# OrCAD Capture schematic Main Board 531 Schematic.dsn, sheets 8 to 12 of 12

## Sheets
8 08 COMET SYSTEM: size A3; title: COMET10 EVAL board - Clock, JTAG, SPI0, Tamper
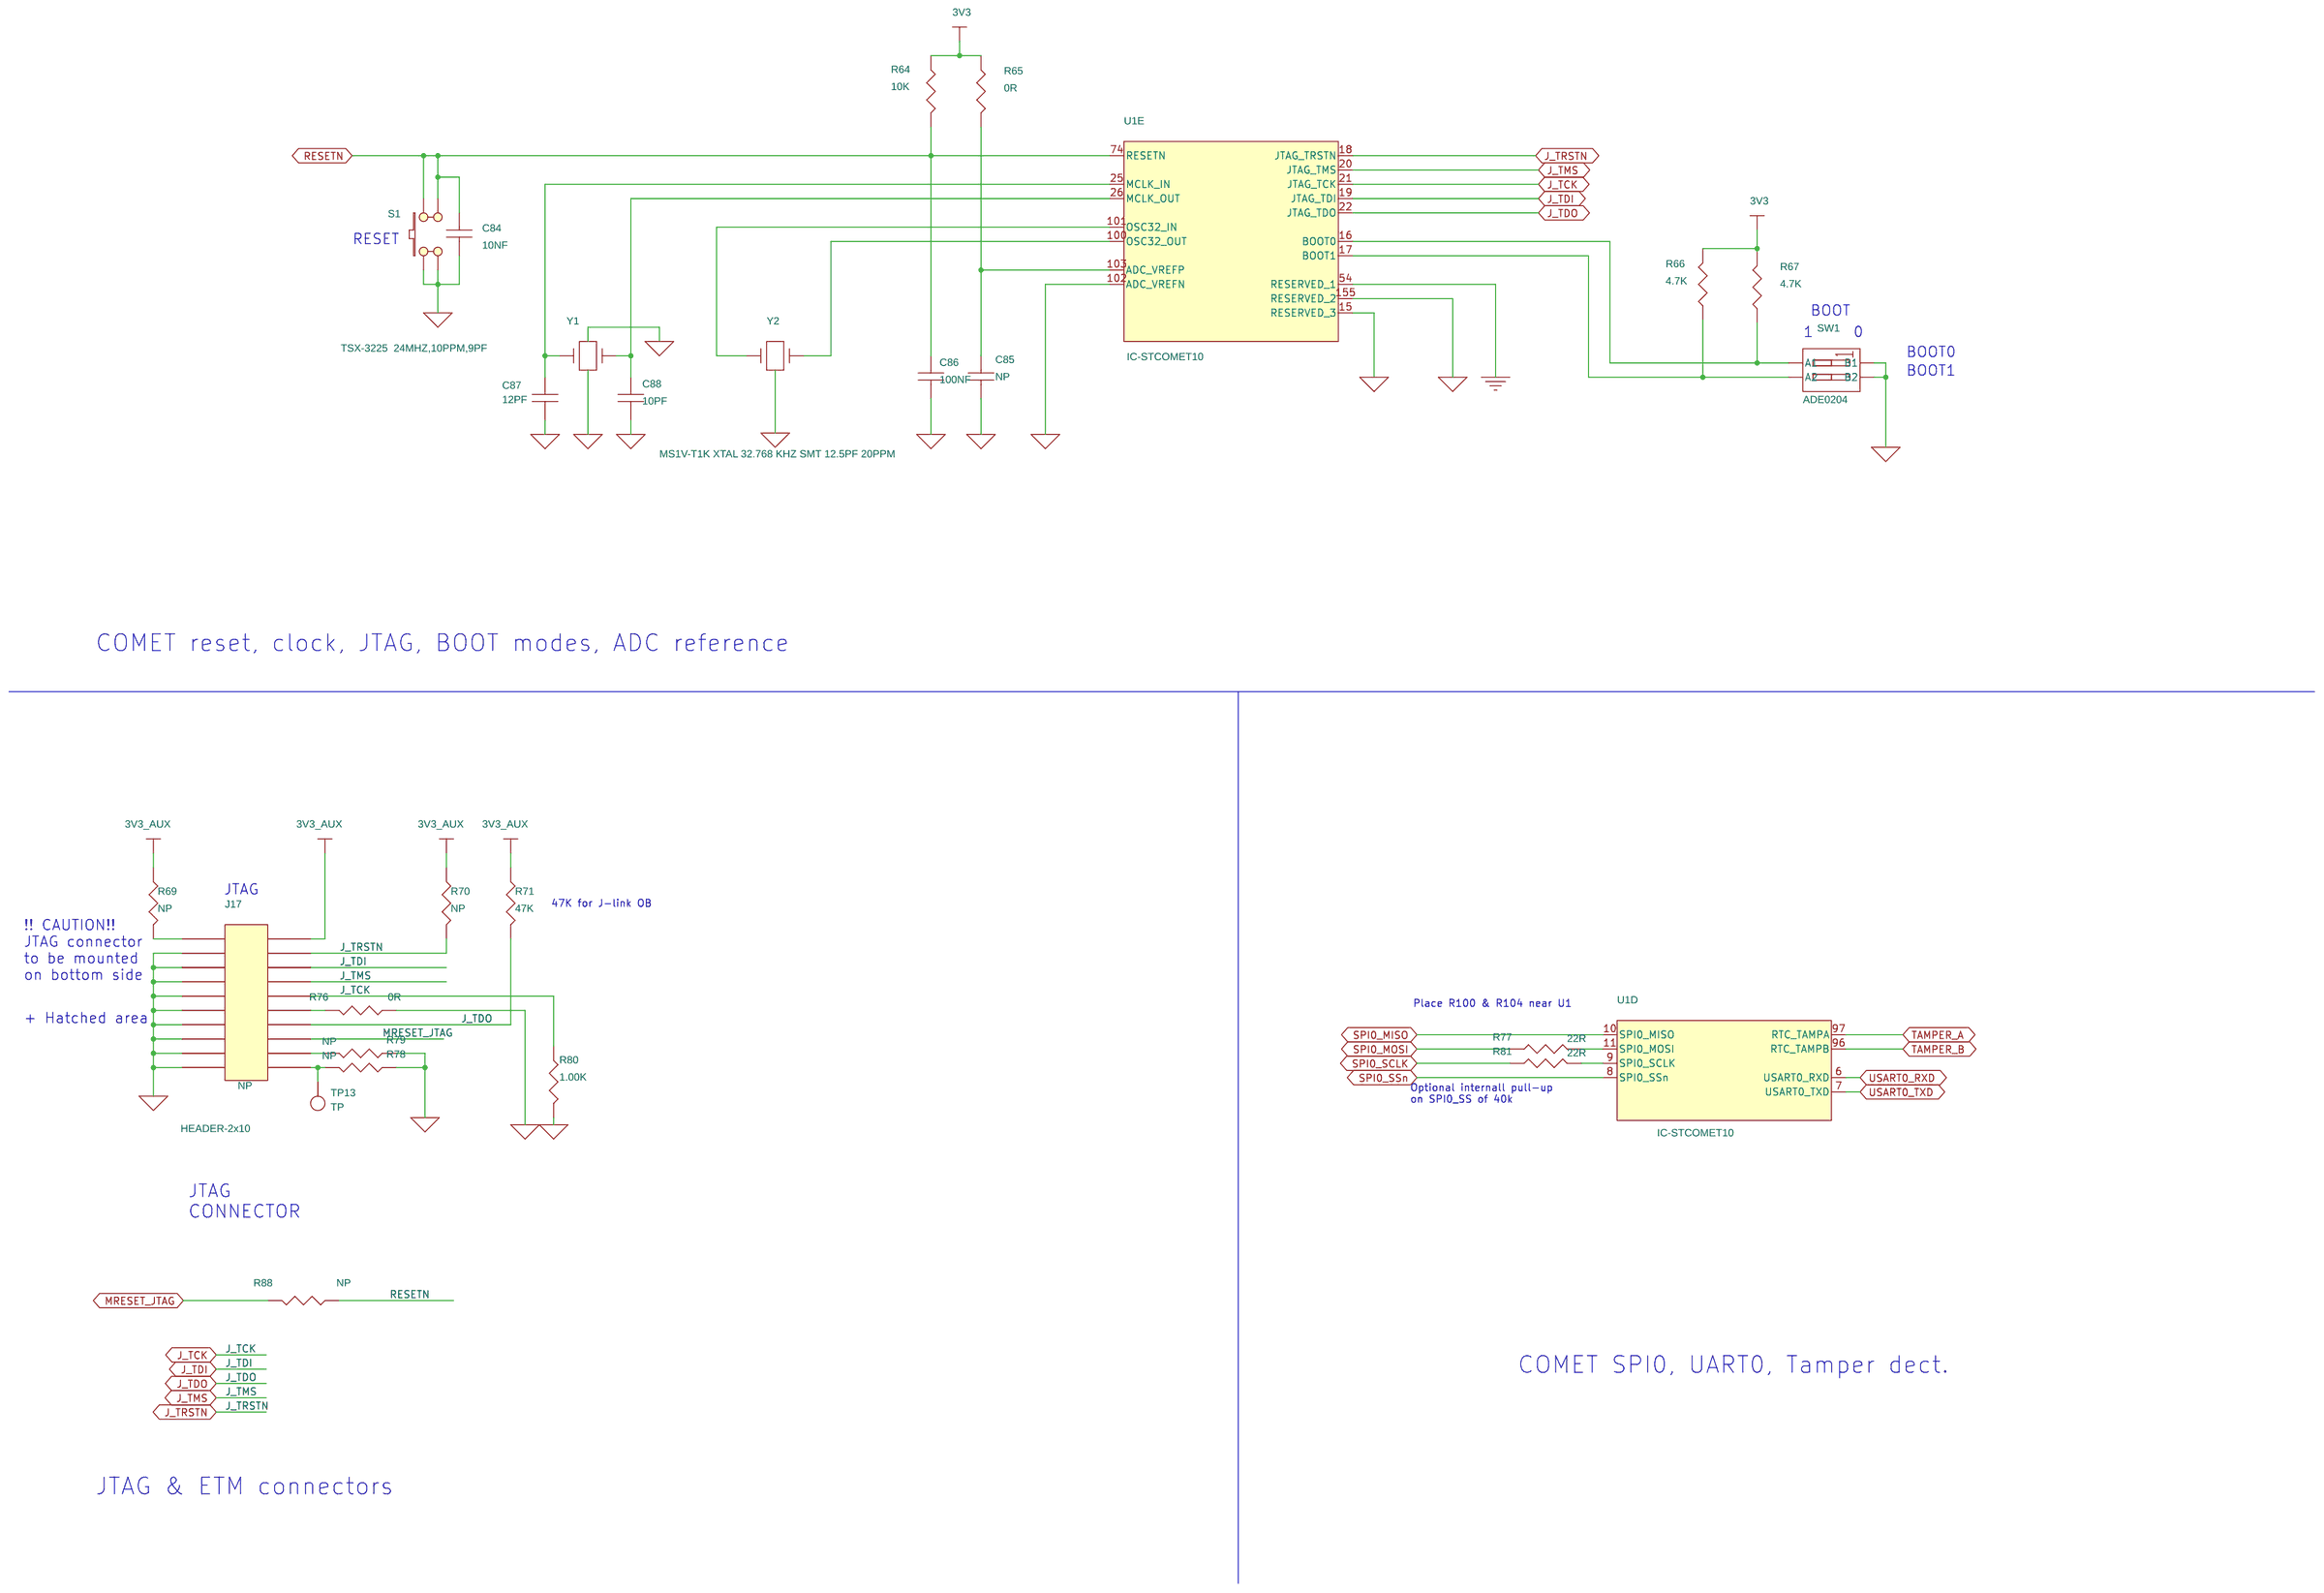
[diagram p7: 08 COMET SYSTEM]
9 09 COMET GPIO: size A3; title: COMET10 EVAL board - COMET GPIOs
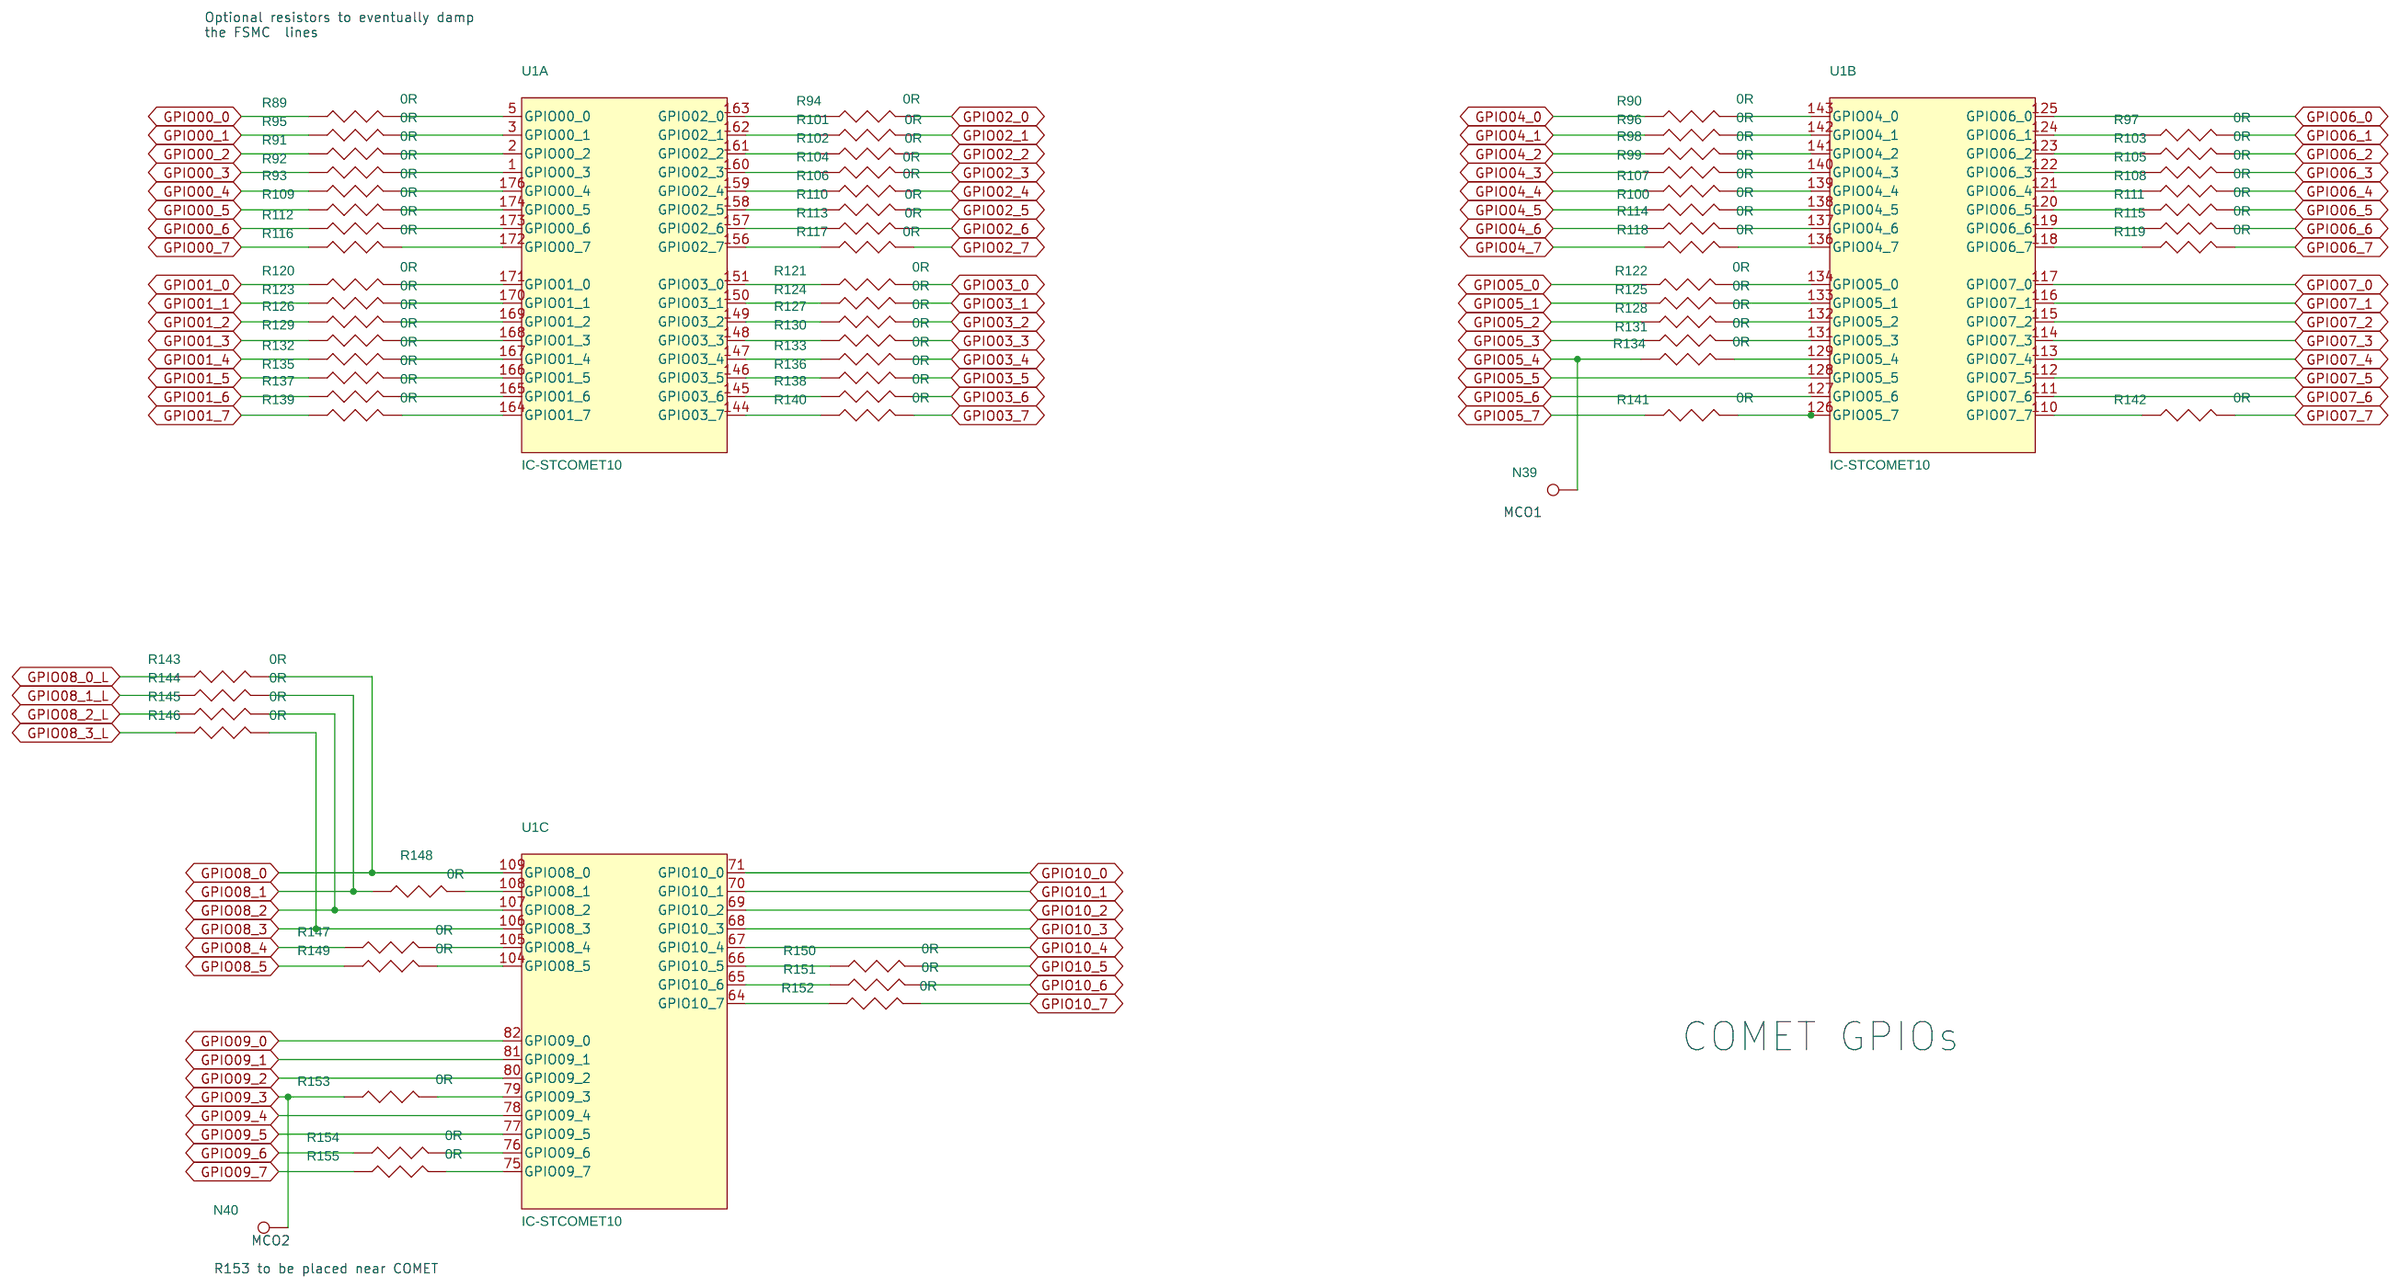
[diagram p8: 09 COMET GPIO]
10 10 MODULE-CONNECTOR: size A3; title: COMET10 EVAL board -  MODULE connector
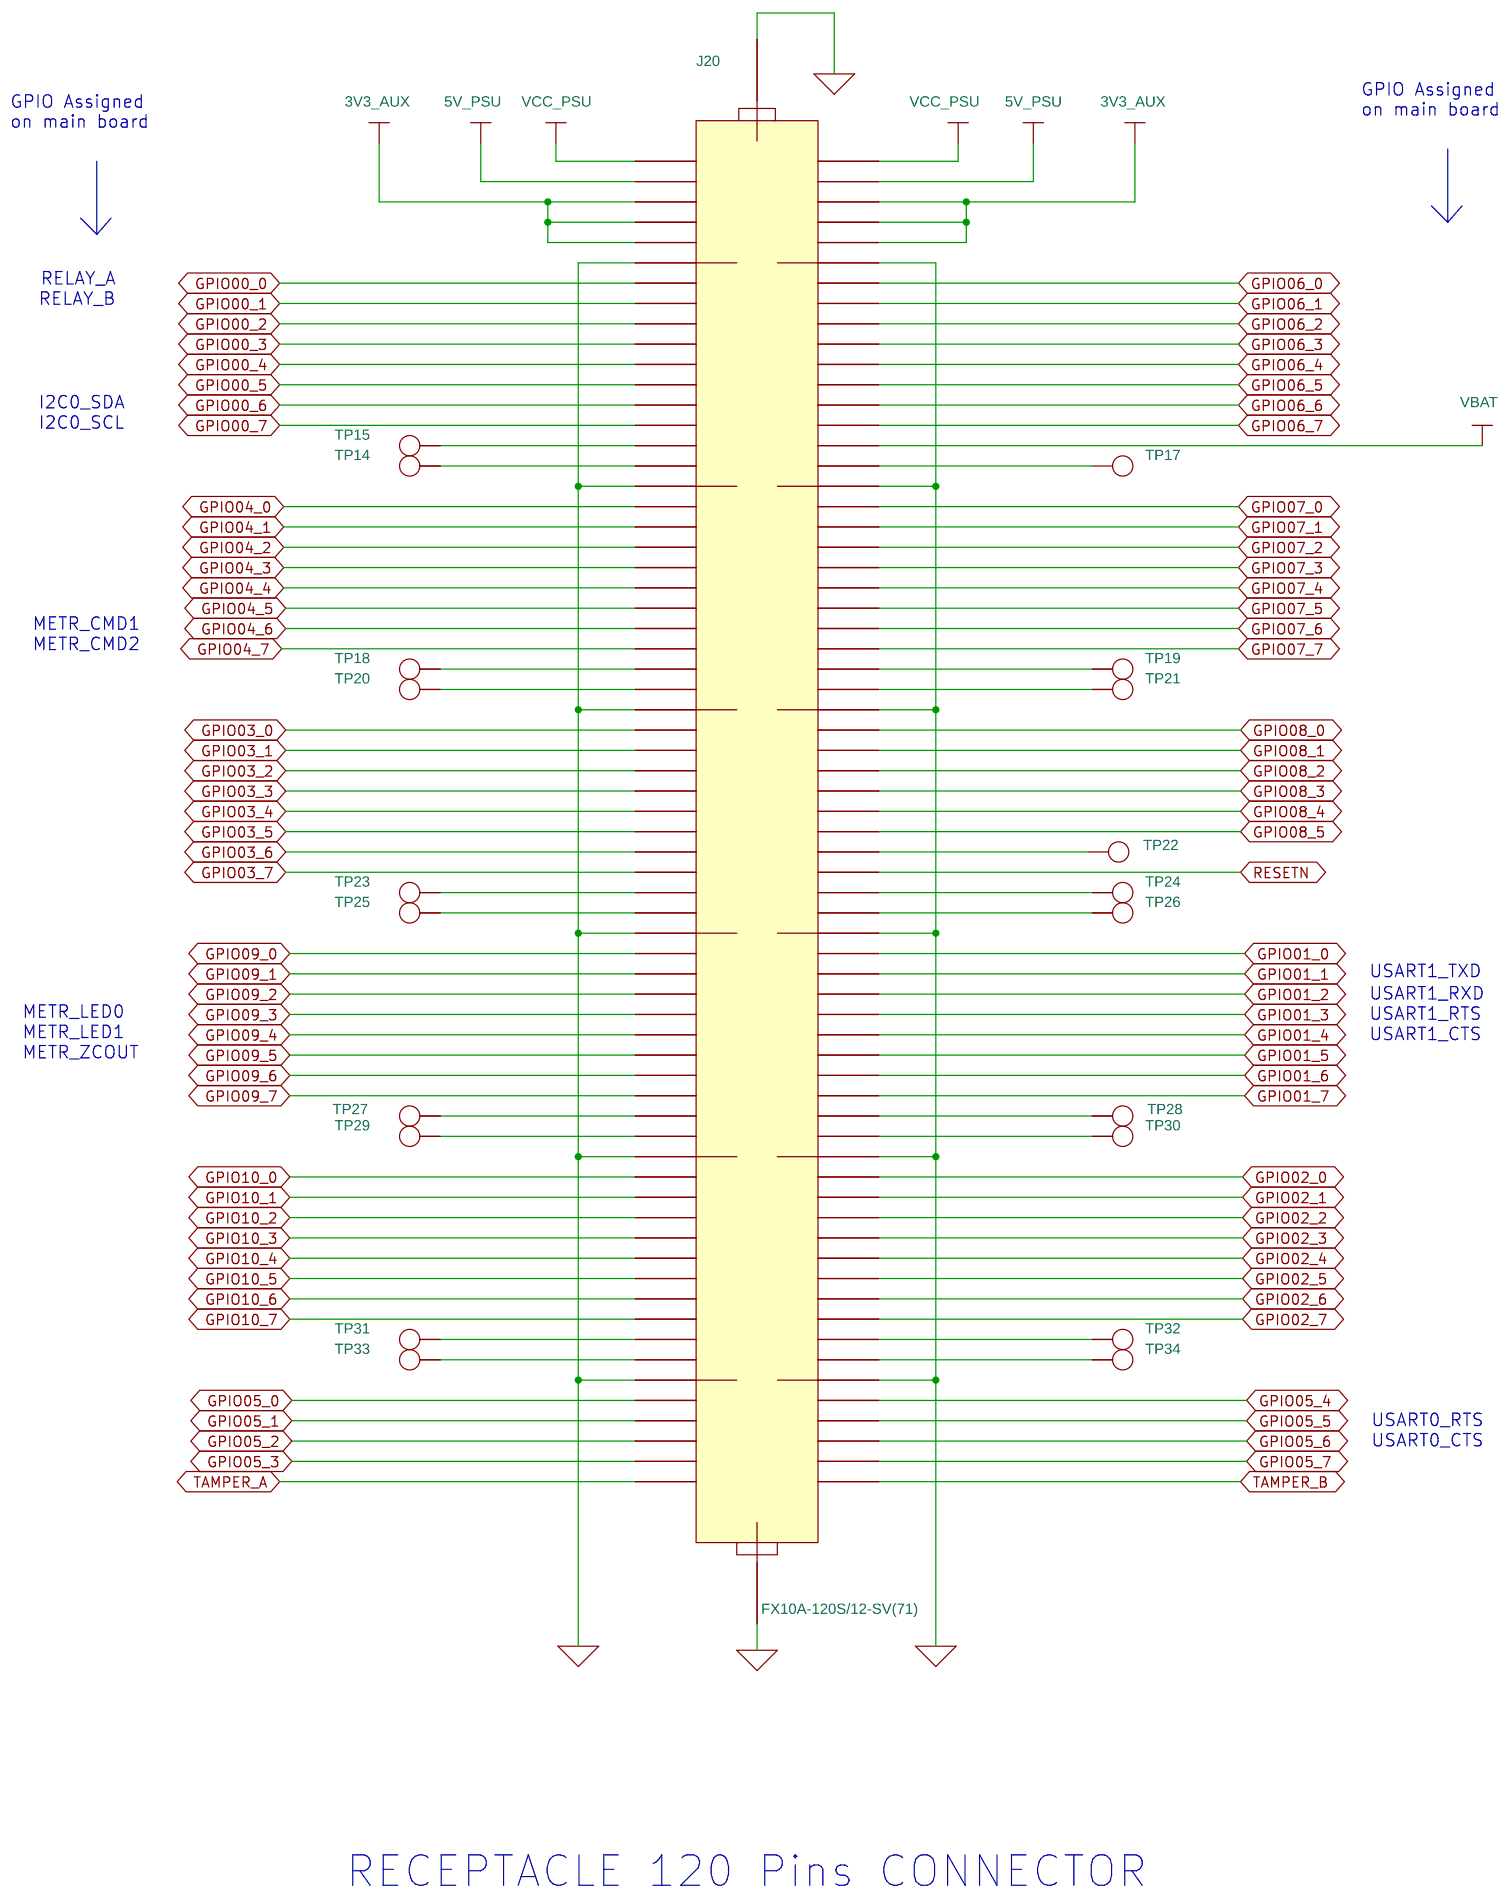
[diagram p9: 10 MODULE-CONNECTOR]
11 11 UART  Switch&Leds: size A3; title: COMET10 EVAL board - USB UART bridge,  DIP Switch&LEDs,EEPROM, SPI FLASH
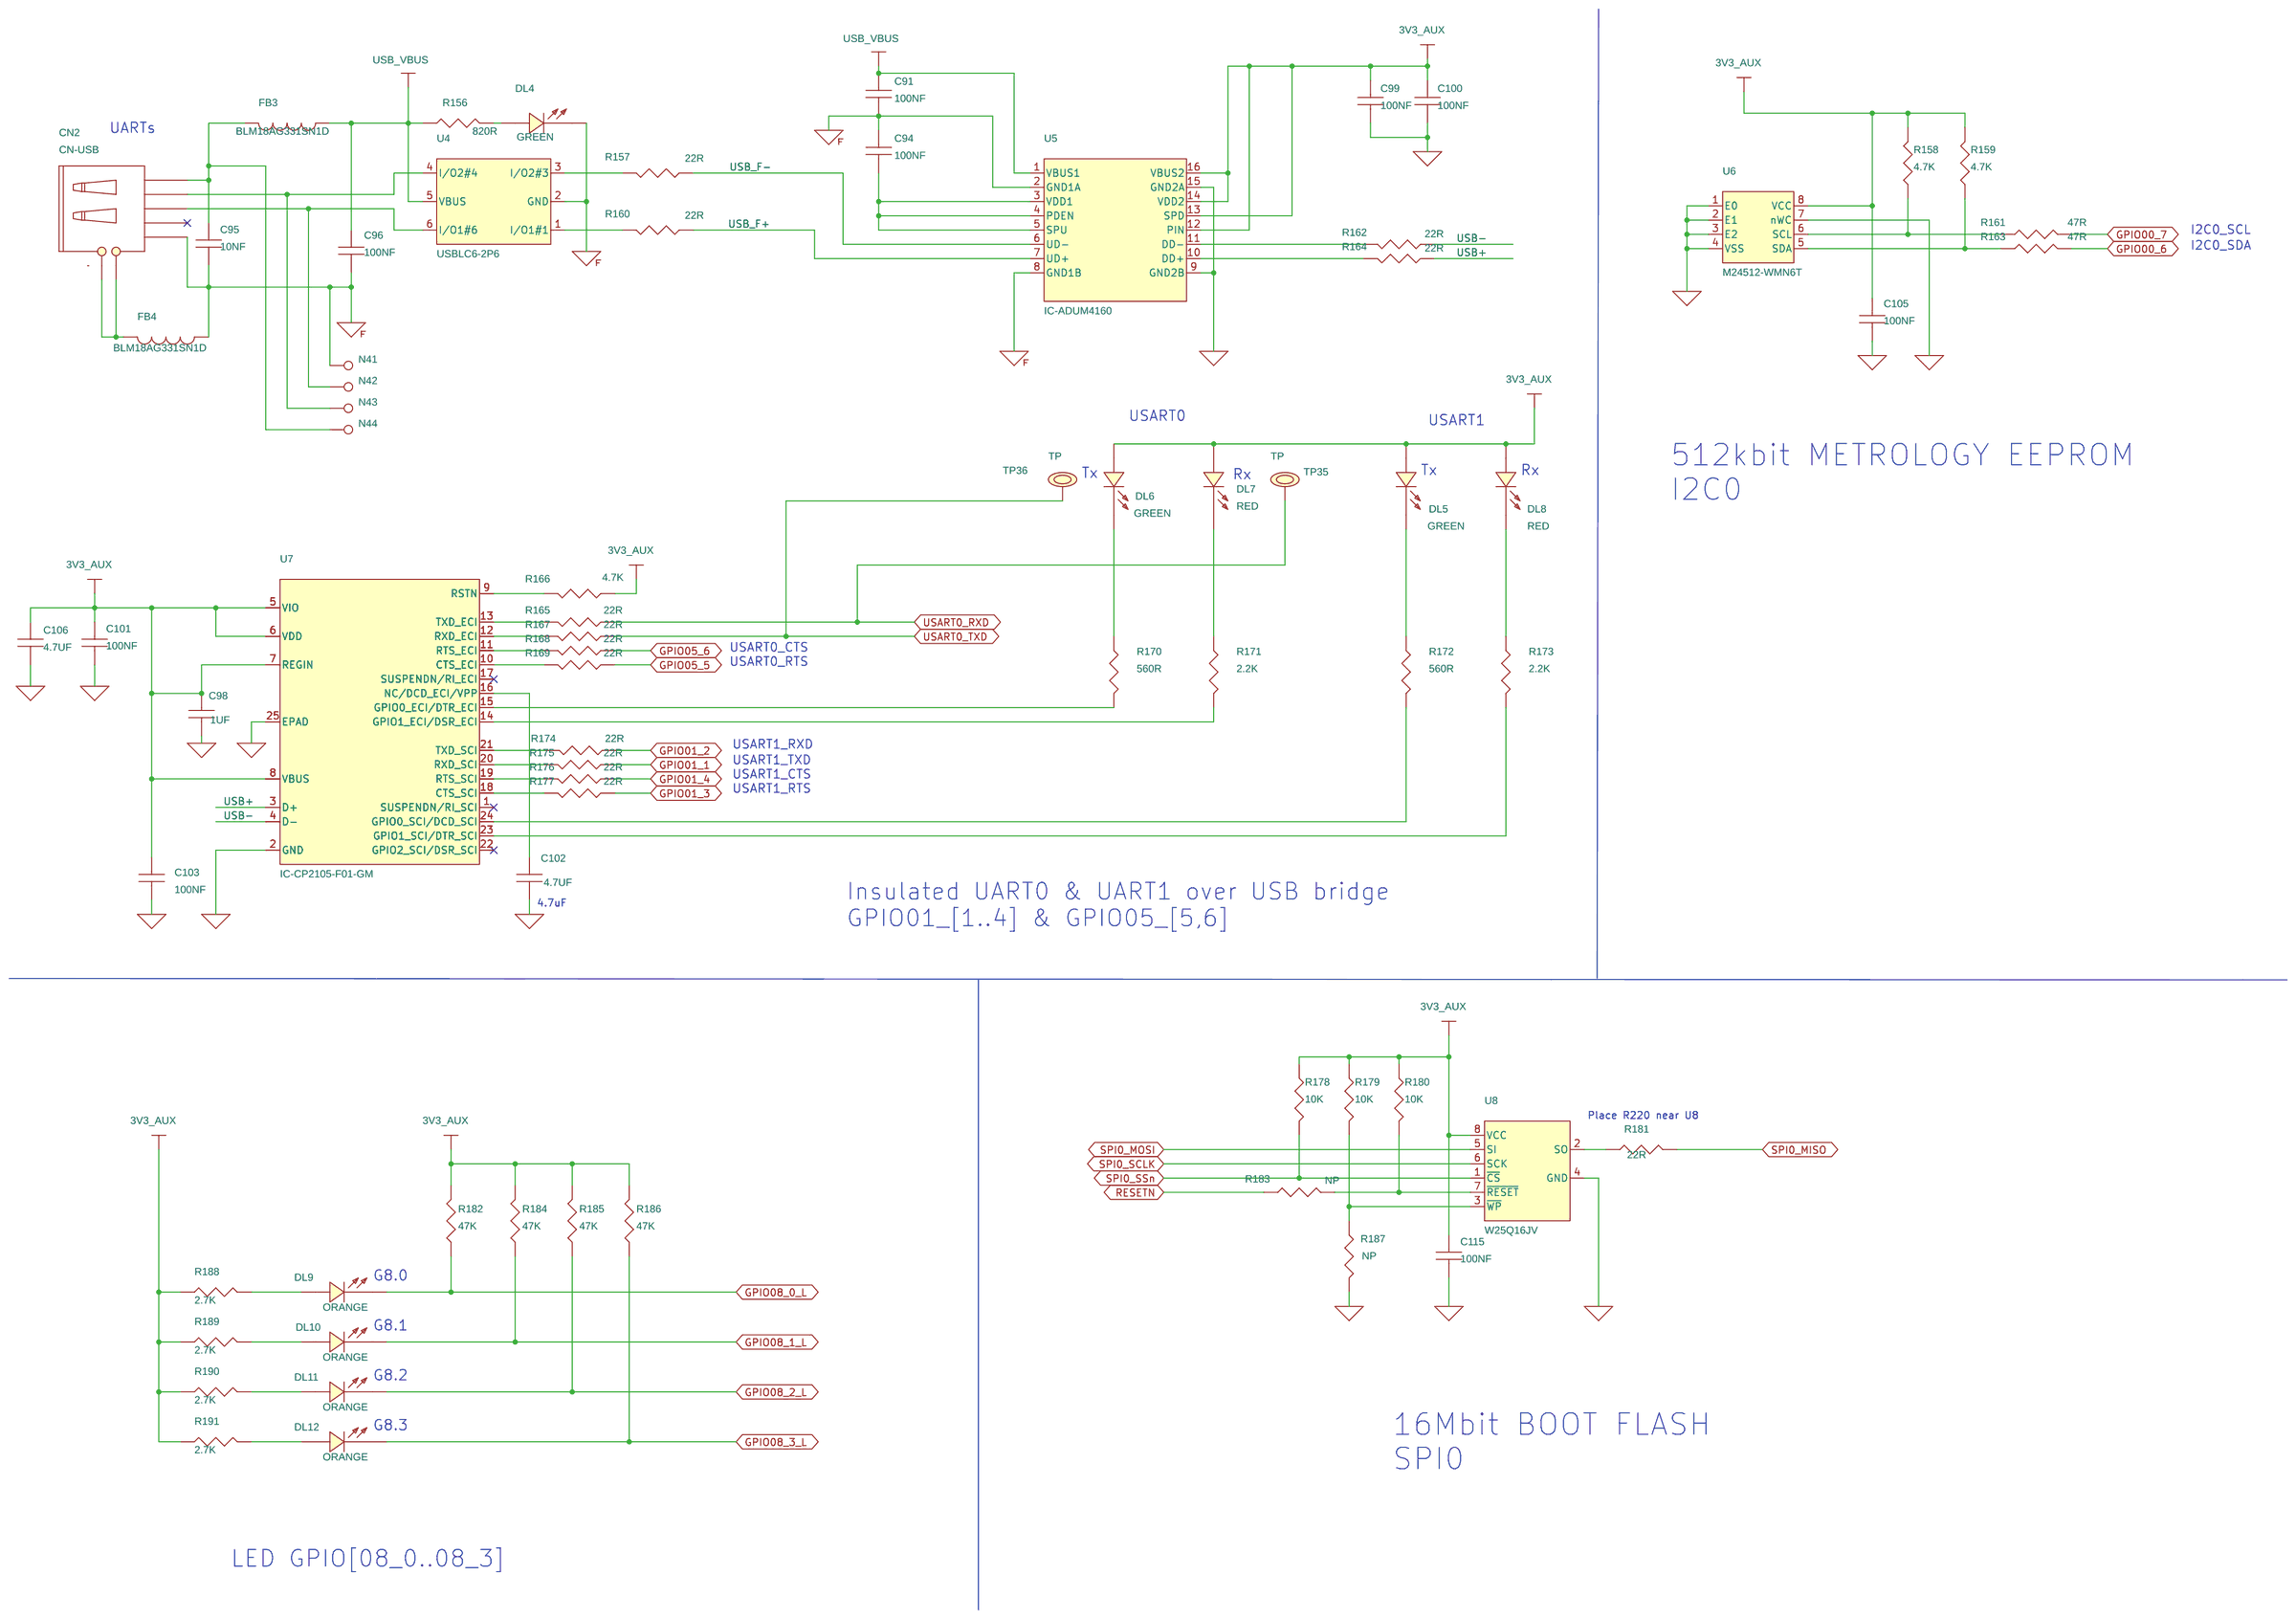
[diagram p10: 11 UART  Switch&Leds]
12 12 J-LINK OB JTAG: size A3; title: COMET10 EVAL Board -  J-LINK OB JTAG
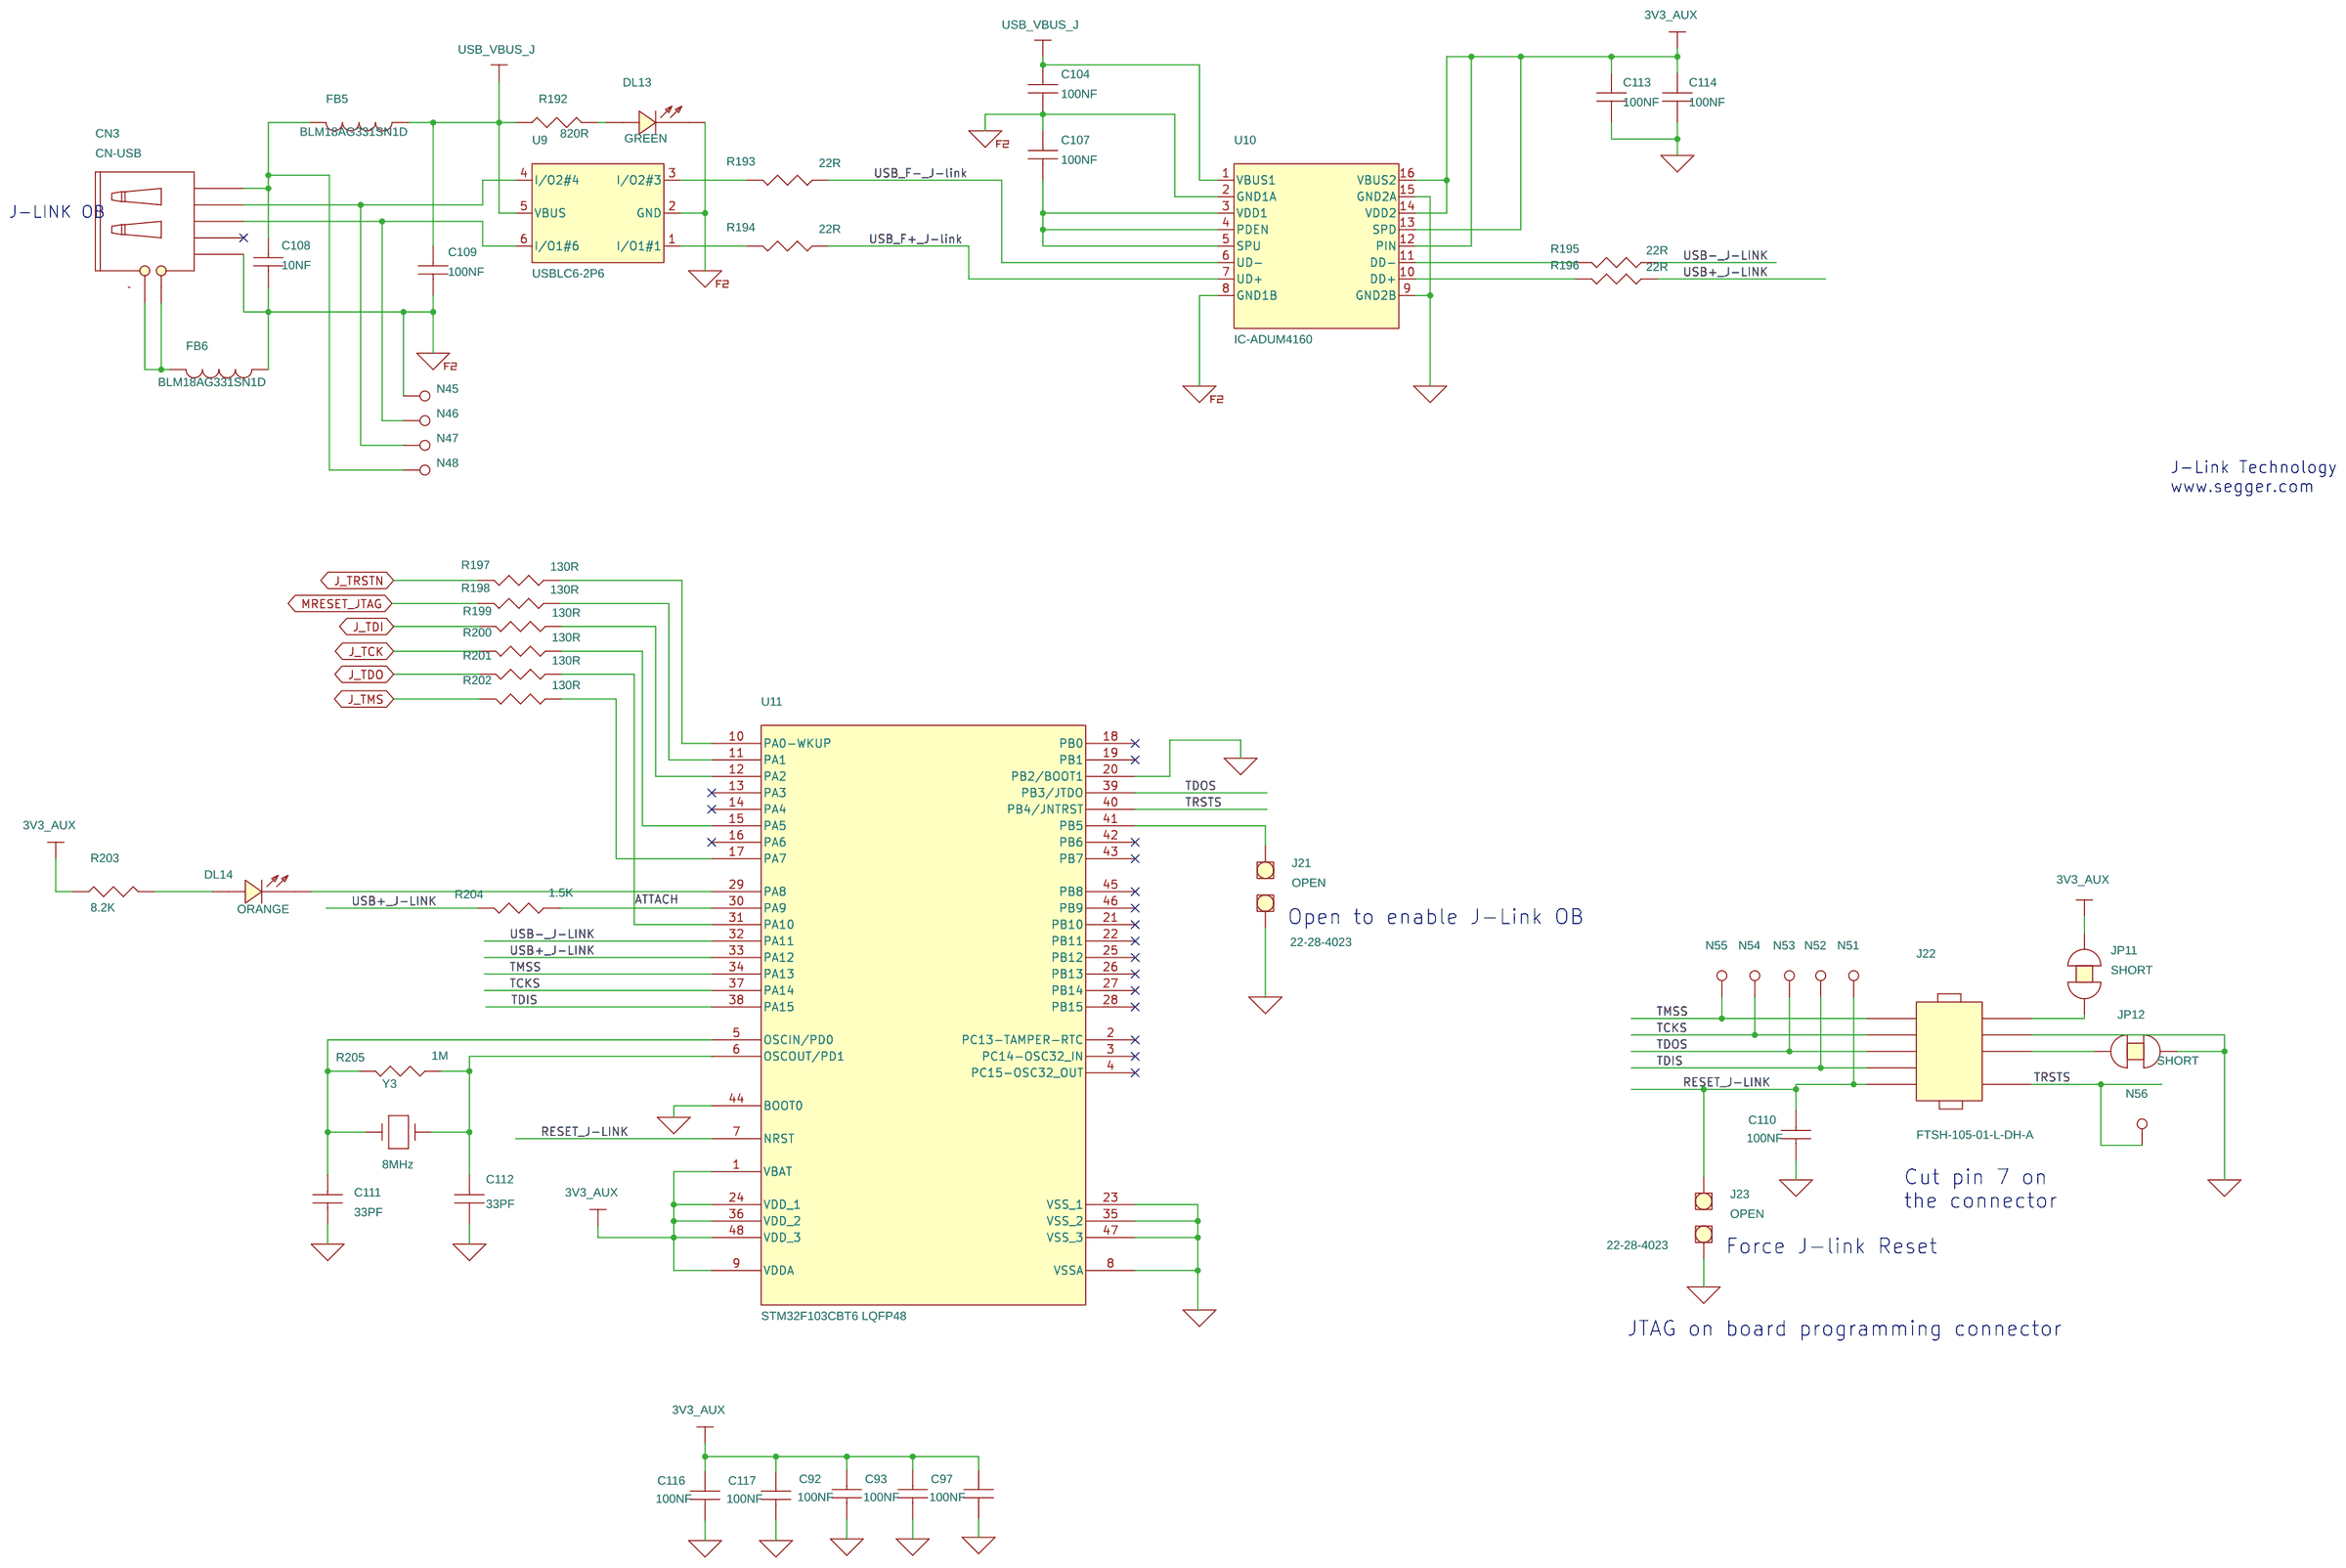
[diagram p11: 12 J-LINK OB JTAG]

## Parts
sheet 04 COMET METROLOGY
U1  IC-STCOMET10  [TQFP176  0.4picth 20*20]  (sections A,B,C,D,E,F,G,H,I,J,K)
sheet 08 COMET SYSTEM
C84  10NF  [0603]
C85  NP  [0402]
C86  100NF  [0402]
C87  12PF  [0603]
C88  10PF  [0603]
J17  NP  [HEADER-2x10]
R64  10K  [0603]
R65  0R  [0603]
R66  4.7K  [0603]
R67  4.7K  [0603]
R69  NP  [0603]
R70  NP  [0603]
R71  47K  [0603]
R76  0R  [0603]
R77  22R  [0603]
R78  NP  [0603]
R79  NP  [0603]
R80  1.00K  [0603]
R81  22R  [0603]
R88  NP  [0603]
S1  EVQQ2H03W  [BUTTON-EVQQ2]
SW1  ADE0204
TP13  TP  [TPSMD-40RD]
Y1  TSX-3225  24MHZ,10PPM,9PF  [OSC-320X250X100-4PIN]
Y2  MS1V-T1K XTAL 32.768 KHZ SMT 12.5PF 20PPM  [XTAL-MS1VT1K]
sheet 09 COMET GPIO
N39  TP  [TPSMD-40RD]
N40  TP  [TPSMD-40RD]
R89  0R  [0603]
R90  0R  [0603]
R91  0R  [0603]
R92  0R  [0603]
R93  0R  [0603]
R94  0R  [0603]
R95  0R  [0603]
R96  0R  [0603]
R97  0R  [0603]
R98  0R  [0603]
R99  0R  [0603]
R100  0R  [0603]
R101  0R  [0603]
R102  0R  [0603]
R103  0R  [0603]
R104  0R  [0603]
R105  0R  [0603]
R106  0R  [0603]
R107  0R  [0603]
R108  0R  [0603]
R109  0R  [0603]
R110  0R  [0603]
R111  0R  [0603]
R112  0R  [0603]
R113  0R  [0603]
R114  0R  [0603]
R115  0R  [0603]
R116  0R  [0603]
R117  0R  [0603]
R118  0R  [0603]
R119  0R  [0603]
R120  0R  [0603]
R121  0R  [0603]
R122  0R  [0603]
R123  0R  [0603]
R124  0R  [0603]
R125  0R  [0603]
R126  0R  [0603]
R127  0R  [0603]
R128  0R  [0603]
R129  0R  [0603]
R130  0R  [0603]
R131  0R  [0603]
R132  0R  [0603]
R133  0R  [0603]
R134  0R  [0603]
R135  0R  [0603]
R136  0R  [0603]
R137  0R  [0603]
R138  0R  [0603]
R139  0R  [0603]
R140  0R  [0603]
R141  0R  [0603]
R142  0R  [0603]
R143  0R  [0603]
R144  0R  [0603]
R145  0R  [0603]
R146  0R  [0603]
R147  0R  [0603]
R148  0R  [0603]
R149  0R  [0603]
R150  0R  [0603]
R151  0R  [0603]
R152  0R  [0603]
R153  0R  [0603]
R154  0R  [0603]
R155  0R  [0603]
sheet 10 MODULE-CONNECTOR
J20  FX10A-120S/12-SV(71)  [FX10A-120S/12-SV(71)-COMET]
TP14  TP  [TPSMD-40RD]
TP15  TP  [TPSMD-40RD]
TP17  TP  [TPSMD-40RD]
TP18  TP  [TPSMD-40RD]
TP19  TP  [TPSMD-40RD]
TP20  TP  [TPSMD-40RD]
TP21  TP  [TPSMD-40RD]
TP22  TP  [TPSMD-40RD]
TP23  TP  [TPSMD-40RD]
TP24  TP  [TPSMD-40RD]
TP25  TP  [TPSMD-40RD]
TP26  TP  [TPSMD-40RD]
TP27  TP  [TPSMD-40RD]
TP28  TP  [TPSMD-40RD]
TP29  TP  [TPSMD-40RD]
TP30  TP  [TPSMD-40RD]
TP31  TP  [TPSMD-40RD]
TP32  TP  [TPSMD-40RD]
TP33  TP  [TPSMD-40RD]
TP34  TP  [TPSMD-40RD]
sheet 11 UART  Switch&Leds
C91  100NF  [0402]
C94  100NF  [0402]
C95  10NF  [0603]
C96  100NF  [0402]
C98  1UF  [0603]
C99  100NF  [0402]
C100  100NF  [0402]
C101  100NF  [0402]
C102  4.7UF  [0603]
C103  100NF  [0402]
C105  100NF  [0402]
C106  4.7UF  [0603]
C115  100NF  [0402]
CN2  CN-USB  [USBMB-HRS-UX60SC]
DL4  GREEN  [LEDC-0603]
DL5  GREEN  [LEDC-0603]
DL6  GREEN  [LEDC-0603]
DL7  RED  [LEDC-0603]
DL8  RED  [LEDC-0603]
DL9  ORANGE  [LEDC-0603]
DL10  ORANGE  [LEDC-0603]
DL11  ORANGE  [LEDC-0603]
DL12  ORANGE  [LEDC-0603]
FB3  BLM18AG331SN1D  [0603]
FB4  BLM18AG331SN1D  [0603]
N41  TP  [TPSMD-40RD]
N42  TP  [TPSMD-40RD]
N43  TP  [TPSMD-40RD]
N44  TP  [TPSMD-40RD]
R156  820R  [0603]
R157  22R  [0603]
R158  4.7K  [0603]
R159  4.7K  [0603]
R160  22R  [0603]
R161  47R  [0603]
R162  22R  [0603]
R163  47R  [0603]
R164  22R  [0603]
R165  22R  [0603]
R166  4.7K  [0603]
R167  22R  [0603]
R168  22R  [0603]
R169  22R  [0603]
R170  560R  [0603]
R171  2.2K  [0603]
R172  560R  [0603]
R173  2.2K  [0603]
R174  22R  [0603]
R175  22R  [0603]
R176  22R  [0603]
R177  22R  [0603]
R178  10K  [0603]
R179  10K  [0603]
R180  10K  [0603]
R181  22R  [0603]
R182  47K  [0603]
R183  NP  [0603]
R184  47K  [0603]
R185  47K  [0603]
R186  47K  [0603]
R187  NP  [0603]
R188  2.7K  [0603]
R189  2.7K  [0603]
R190  2.7K  [0603]
R191  2.7K  [0603]
TP35  TP  [TPTH-ANELLO-1MM]
TP36  TP  [TPTH-ANELLO-1MM]
U4  USBLC6-2P6  [SOT-666]
U5  IC-ADUM4160  [SOC16]
U6  M24512-WMN6T  [SO8]
U7  IC-CP2105-F01-GM  [QFN050P-400X400X080-24-EP]
U8  W25Q16JV  [8NSOIC]
sheet 12 J-LINK OB JTAG
C92  100NF  [0402]
C93  100NF  [0402]
C97  100NF  [0402]
C104  100NF  [0402]
C107  100NF  [0402]
C108  10NF  [0603]
C109  100NF  [0402]
C110  100NF  [0402]
C111  33PF  [0603]
C112  33PF  [0603]
C113  100NF  [0402]
C114  100NF  [0402]
C116  100NF  [0402]
C117  100NF  [0402]
CN3  CN-USB  [USBMB-HRS-UX60SC]
DL13  GREEN  [LEDC-0603]
DL14  ORANGE  [LEDC-0603]
FB5  BLM18AG331SN1D  [0603]
FB6  BLM18AG331SN1D  [0603]
J21  OPEN  [22-28-4023]
J22  FTSH-105-01-L-DH-A  [FTSH-105-01-L-DH-A]
J23  OPEN  [22-28-4023]
JP11  SHORT  [JP2SO]
JP12  SHORT  [JP2SO]
N45  TP  [TPSMD-40RD]
N46  TP  [TPSMD-40RD]
N47  TP  [TPSMD-40RD]
N48  TP  [TPSMD-40RD]
N51  TP  [TPSMD-40RD]
N52  TP  [TPSMD-40RD]
N53  TP  [TPSMD-40RD]
N54  TP  [TPSMD-40RD]
N55  TP  [TPSMD-40RD]
N56  TP  [TPSMD-40RD]
R192  820R  [0603]
R193  22R  [0603]
R194  22R  [0603]
R195  22R  [0603]
R196  22R  [0603]
R197  130R  [0603]
R198  130R  [0603]
R199  130R  [0603]
R200  130R  [0603]
R201  130R  [0603]
R202  130R  [0603]
R203  8.2K  [0603]
R204  1.5K  [0603]
R205  1M  [0603]
U9  USBLC6-2P6  [SOT-666]
U10  IC-ADUM4160  [SOC16]
U11  STM32F103CBT6 LQFP48  [LQFP48]
Y3  8MHz  [ATS08ASM]

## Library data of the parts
U1 = IC-COMET10: Manufacturer: STMICROELECTRONICS; Package_Type: COMET10
C84 C95 C108 = CAP_NP: CAP CER 10nF 25V X7R 0603; Manufacturer: AVX; Manufacturer Part Number: 06033C103KAT2A; PSpice: C; Package_Type: C0603; Part Number: 06033C103KAT2A; Part Type: CERAMIC; Tolerance: 10%; Voltage: 25V
C85 = CAP_NP: CAP NP 0402; PSpice: C; Package_Type: C0402; Part Number: C_NP_0402
C86 C91-C94 C96 C97 C99-C101 C103-C105 C107 C109 C110 C113-C117 = CAP_NP: CAP CER 100nF 16V X7R 0402; Manufacturer: MURATA; Manufacturer Part Number: GRM155R71C104KA88D; PSpice: C; Package_Type: C0402; Part Number: GRM155R71C104KA88D; Part Type: CERAMIC; Tolerance: 10%; Voltage: 16V
C87 = CAP_NP: CAP CER 12pF 50V COG 0603; PSpice: C; Package_Type: C0603; Part Number: 12PF_50V_COG_0603; Part Type: CERAMIC; Tolerance: 10%; Voltage: 50V
C88 = CAP_NP: CAP CER 10PF 50V COG 0603; PSpice: C; Package_Type: C0603; Part Number: 10PF_50V_COG_0603; Part Type: CERAMIC; Tolerance: 10%; Voltage: 50V
J17 = HTST-110-01-T-DV_0: CON-RIGHT ANGLE-10X2-180M; Distributor: FARNELL; Distributor Part Number: 1801424; Manufacturer: SAMTEC; Manufacturer Part Number: TST-110-04-L-D; Package_Type: TST-110-04-L-D; Part Number: TST-110-04-L-D_NP; Datasheet: http://www.samtec.com/ftppub/cpdf/TST-MKT.pdf
R64 R178-R180 = R: RES 10K OHM 5% 1/10W 0603 SMD; Package_Type: R0603; Part Number: 10K_5%_0603; Part type: CMS; Power: 1/10W; Tolerance: 5%
R65 R76 R89-R155 = R: 0.0 OHM 5% 1/10W 0603; Manufacturer: YAGEO; Manufacturer Part Number: RC0603JR-070RL; Package_Type: R0603; Part Number: RC0603JR-070RL; Part type: CMS; Power: 1/10W; Tolerance: 5%
R66 R67 R158 R159 R166 = R: 4.7K OHM 5% 1/10W; Manufacturer: PANASONIC CORP; Manufacturer Part Number: ERJ-3GEYJ472V; Package_Type: R0603; Part Number: ERJ-3GEYJ472V; Part type: CMS; Power: 1/10W; Tolerance: 5%
R69 R70 R78 R79 R88 R183 R187 = R: RES NP 0603; Package_Type: R0603; Part Number: R_NP_0603; Part type: CMS
R71 R182 R184-R186 = R: 47K OHM 1% 1/10W; Manufacturer: PANASONIC CORP; Manufacturer Part Number: ERJ-3EKF4702V; Package_Type: R0603; Part Number: ERJ-3EKF4702V; Part type: CMS; Power: 1/10W; Tolerance: 1%
R77 R81 R157 R160 R162 R164 R165 R167-R169 R174-R177 R181 R193-R196 = R: RES 22.0 OHM 1/10W 5% 0603 SMD; Package_Type: R0603; Part Number: 22R_5%_0603; Part type: CMS; Power: 1/10W; Tolerance: 5%
R80 = R: RESISTOR,  1.00K OHM 1/10W 1% 0603 SMD; ActivepartsID: http://CDS2.ORCAD.COM/default.asp?PID=1783654; ICA_MFR_NAME: PANASONIC CORP; ICA_PARTNUM: $$1783654$$ERJ-3EKF1001V; Manufacturer: PANASONIC CORP; Manufacturer Part Number: ERJ-3EKF1001V; Package_Type: R0603; Part Number: ERJ-3EKF1001V; Part type: CMS; Power: 1/10W; Tolerance: 1%; Datasheet: http://www.panasonic.com/industrial_oem/electronic_components/pdf/erj_precision.pdf
S1 = PULSANTE-EVQQ2_0: SWITCH BUTTON SMD; Distributor: Farnell; Distributor Part Number: 1821248; Manufacturer: PANASONIC CORP; Package_type: BUTTON_EVQQ2; Datasheet: http://fr.farnell.com/panasonic/evqq2h03w/switch-smd-6-5x6x3-1mm-1n/dp/1821248
SW1 = DIPSW-2Channels: DIP Switch 2 channels; Distributor: Farnell; Distributor Part Number: 1123936; Manufacturer: TE CONNECTIVITY; Datasheet: http://www.farnell.com/datasheets/17891.pdf
TP13-TP15 TP17-TP34 = TPSMD-40RD: Point Test PCB TPSMD-40RD
Y1 = XTAL-TSX-3225_0: XTAL,24MHZ,10PPM,9PF; Manufacturer: MICRO CRYSTAL; Manufacturer Part Number: MS1VT1K; Package_type: OSC-EPSON-TSX3225; Part Number: TSX-3225_0; Tolerance: 10PPM; Datasheet: http://fr.farnell.com/micro-crystal/ms1v-t1k-32-768khz-20ppm-12-5pf/crystal-smd-met-32-768khz-12-5/dp/1539359
Y2 = XTAL-MS1VT1K: XTAL 32.768 KHZ SMT 12.5PF 20PPM; Distributor: RS; Distributor Part Number: 672-7590; Manufacturer: Micro Crystal; Manufacturer Part Number: MS1V-T1K 32.768kHz 12.5pF +-20ppm; Part Number: MS1V-T1K 32.768kHz 12.5pF +-20ppm; Tolerance: 20PPM; Datasheet: http://docs-europe.electrocomponents.com/webdocs/0d2c/0900766b80d2cbaf.pdf
N39-N48 N51-N56 = NEEDLE_PAD: Pad 1.7mm for test needle; Package_Type: TPSMD-1.7MM; Part Number: NEEDLE-PAD-1.7mm
J20 = CON-FX10-120P-F-GND: CONN 120P high density EMBASE RECEPTACLE. 0.5MM. GUIDE. 120 VOIES, with reversed pins for COMET; Manufacturer: HIROSE; Package_Type: FX10A-120S/12-SV_COMET; Part Number: FX10A-120S/12-SV(71)-COMET-Mother; Datasheet: \\pouilly.rns.st.com\home\_RDC\External_DataSheet\Connectors\Board_to_Board\Hirose\FXxx\en_FX10_20110101.pdf
C98 = CAP_NP: CAP CER 1UF 10V X7R 0603; PSpice: C; Package_Type: C0603; Part Number: 1UF_10V_X7R_0603; Part Type: CERAMIC; Tolerance: 15%; Voltage: 10V
C102 C106 = CAP_NP: CAP CER 4.7UF 6V3 X5R 0603; PSpice: C; Package_Type: C0603; Part Number: 4.7UF_6V3_X5R_0603; Part Type: CERAMIC; Tolerance: 15%; Voltage: 6.3V
CN2 CN3 = USBMB-HRS-UX60SC: CONN Mini USB2.0 SMT; Distributor: FARNELL; Distributor Part Number: 2300434; Manufacturer: HIROSE; Manufacturer Part Number: UX60SC-MB-5ST; Package_Type: CON-USB-MOLEX-54819-0519; Part Number: UX60SC-MB-5ST; Datasheet: http://uk.farnell.com/hrs-hirose/ux60sc-mb-5st-80/connector-mini-usb-b-receptacle/dp/2300434?Ntt=2300434
DL4-DL6 DL13 = LED: GREEN LEDC-0603; Distributor: RS; Distributor Part Number: 692-1007; Manufacturer: LITE-ON; Manufacturer Part Number: LTST-C191GKT; Package_Type: LEDC-0603_GREEN; Part Number: LED_GREEN_0603_2mA; Datasheet: http://docs-europe.electrocomponents.com/webdocs/0dc0/0900766b80dc02af.pdf
DL7 DL8 = LED: RED LEDC-0603; Distributor: RS; Distributor Part Number: 692-1041; Manufacturer: LITE-ON; Manufacturer Part Number: LTST-C193KRKT-5A; Package_Type: LEDC-0603_RED; Part Number: LED_RED_0603_2mA; Datasheet: http://docs-europe.electrocomponents.com/webdocs/0dc0/0900766b80dc0551.pdf
DL9-DL12 DL14 = LED: ORANGE LEDC-0603; Distributor: RS; Distributor Part Number: 692-1001; Manufacturer: LITE-ON; Manufacturer Part Number: LTST-C191KFKT; Package_Type: LEDC-0603_ORANGE; Part Number: LED_ORANGE_0603_2mA; Datasheet: http://docs-europe.electrocomponents.com/webdocs/0dc0/0900766b80dc02b0.pdf
FB3-FB6 = INDUCTOR: FERRITE BEAD,330 OHM,0603; Manufacturer: MURATA; Package_Type: L0603; Tolerance: 25%
R156 R192 = R: 820R OHM 5% 1/10W; Package_Type: R0603; Part Number: 820R_5%_0603; Part type: CMS; Power: 1/10W; Tolerance: 5%
R161 R163 = R: RES 47 OHM 1/10W 5% 0603 SMD; Package_Type: R0603; Part Number: 47R_5%_0603; Part type: CMS; Power: 1/10W; Tolerance: 5%
R170 R172 = R: RES 560R OHM 1/10W 5% 0603 SMD; Package_Type: R0603; Part Number: 560R_5%_0603; Part type: CMS; Power: 1/10W; Tolerance: 5%
R171 R173 = R: RES 2.2KOHM 1/10W 5% 0603 SMD; Package_Type: R0603; Part Number: 2.2K_5%_0603; Part type: CMS; Power: 1/10W; Tolerance: 5%
R188-R191 = R: RES 2.7K OHM 5% 1/10W 0603 SMD; Package_Type: R0603; Part Number: 2.7K_5%_0603; Part type: CMS; Power: 1/10W; Tolerance: 5%
TP35 TP36 = TPTH-ANELLO-1MM: Point Test TPTH-ANELLO-1MM black; Distributor: FARNELL; Distributor Part Number: 1463077; Manufacturer: KEYSTONE; Manufacturer Part Number: 534-5001; Datasheet: http://fr.farnell.com/keystone/5001/test-point-connector-black/dp/1463077?Ntt=534-5001
U4 U9 = IC-USBLC6-2P6_0: USBLC6-2P6 - RESEAU DE DIODE TVS USB2; Distributor: RS; Distributor Part Number: 624-7687; Manufacturer: STMICROELECTRONICS; Datasheet: http://fr.farnell.com/jsp/displayProduct.jsp?sku=1295310&CMP=KNC-GFR-FFR-GEN-SKU-G12&mckv=svCk2aUKl|pcrid|15874524782|kword|usblc6-2p6|match|p|plid|
U5 U10 = IC-ADUM4160: ADUM4160, USB ISOLATOR; Distributor: Farnell; Distributor Part Number: 1858056; Manufacturer: Analog Device; Manufacturer Part Number: ADUM4160BRWZ; Package_type: ADUM4160; Part Number: ADUM4160; Datasheet: http://www.farnell.com/datasheets/1700957.pdf
U6 = IC-M24512-WMW6TG: I2C MEMORY SOP127P-620X168-8; Manufacturer: STMICROELECTRONICS; Package_Type: M24512-WMW6TG
U7 = IC-CP2105-F01-GM: Uart over USB bridge, QFN050P; Manufacturer: Silicon Labs; Manufacturer Part Number: CP2105-F01-GM; Package_Type: CP2105-F01-GM; Part Number: CP2105-F01-GM; Datasheet: http://www.silabs.com/Support%20Documents/TechnicalDocs/CP2105.pdf
U8 = IC-M25P16: FLASH SPI W25Q16JV 16MBits WINBOND; Manufacturer: WINBOND; Package_Type: M25P16-VMN6P
C111 C112 = CAP_NP: CAP CER 33pF 50V COG 0603; Manufacturer: MURATA; Manufacturer Part Number: GRM1885C1H330JA01D; PSpice: C; Package_Type: C0603; Part Number: GRM1885C1H330JA01D; Part Type: CERAMIC; Tolerance: 5%; Voltage: 50V; Datasheet: http://docs-europe.electrocomponents.com/webdocs/0873/0900766b808736db.pdf
J21 J23 = JUMP254P-M-2: Manufacturer: MOLEX; Package_Type: JUMPER-OPEN; Part Number: 22-28-4023_O; Datasheet: http://www.molex.com/pdm_docs/sd/022284023_sd.pdf
J22 = STRIP127P-M-5x2-JTAG-SMD: CON 5*2  SMD Right Angle; Manufacturer: SAMTEC; Datasheet: http://www.samtec.com/documents/webfiles/cpdf/FTSH-1XX-XX-XXX-DH-XX-MKT.pdf
JP11 JP12 = JP2SO-SHORT: Solder Bridge with Copper Short; Part Number: Solder Bridge SHORT
R197-R202 = R: RES 130R OHM 1/10W 5% 0603 SMD; Package_Type: R0603; Part Number: 130R_5%_0603; Part type: CMS; Power: 1/10W; Tolerance: 5%
R203 = R: RES 8.2K OHM 5% 1/10W 0603; Package_Type: R0603; Part Number: 8.2K_5%_0603; Part type: CMS; Power: 1/10W; Tolerance: 5%
R204 = R: RES 1.5K OHM 1/10W 5% 0603 SMD; Distributor: FARNELL; Distributor Part Number: 2008356; Package_Type: R0603; Part Number: 1.5K_5%_0603; Part type: CMS; Power: 1/10W; Tolerance: 5%
R205 = R: RES 1M OHM 1/10W 5% 0603 SMD; Package_Type: R0603; Part Number: 1M_5%_0603; Part type: CMS; Power: 1/10W; Tolerance: 5%
U11 = STM32F103CBT6: IC, MCU, RISC, 72 MHz, 3.6V, 32-BIT, 48-PIN, LQFP; Manufacturer: STMICROELECTRONICS; Datasheet: http://www.st.com/st-web-ui/static/active/en/resource/technical/document/datasheet/CD00161566.pdf
Y3 = CRYSTAL: XTAL 8MHz-30PPM-20pF; Distributor: DIGIKEY; Distributor Part Number: CTX1055CT-ND; Manufacturer: CTS; Manufacturer Part Number: ATS08ASM-1E; Package_type: ATS08ASM-1E; Part Number: ATS08ASM-1E; Tolerance: 30PPM; Datasheet: http://www.ctscorp.com/components/Datasheets/008-0309-0.pdf

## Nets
3V3: R64.1 R65.1 R66.1 R67.1 ; also on sheet 6 7
3V3_AUX: C92.1 C93.1 C97.1 C98.1 C99.1 C100.1 C101.1 C103.1 C105.1 C106.1 C113.1 C114.1 C115.1 C116.1 C117.1 DL5.2(ANODE) DL6.2(ANODE) DL7.2(ANODE) DL8.2(ANODE) J17.1 J20.5 J20.6 J20.7 J20.8 J20.9 J20.10 JP11.2 R69.1 R70.1 R71.1 R158.2 R159.2 R166.1 R178.1 R179.1 R180.1 R182.2 R184.2 R185.2 R186.2 R188.1 R189.1 R190.1 R191.1 R203.2 U5.12(PIN) U5.13(SPD) U5.14(VDD2) U5.16(VBUS2) U6.8(VCC) U7.5(VIO) U7.6(VDD) U7.7(REGIN) U7.8(VBUS) U8.8(VCC) U10.12(PIN) U10.13(SPD) U10.14(VDD2) U10.16(VBUS2) U11.1(VBAT) U11.9(VDDA) U11.24(VDD_1) U11.36(VDD_2) U11.48(VDD_3) ; also on sheet 3 6
5V_PSU: J20.3 J20.4 ; also on sheet 6
GND_FIELD SIGNAL_2: C104.2 C107.1 C108.2 C109.2 CN3.5 DL13.1(CATHODE) FB6.2 N45.1 U9.2(GND) U10.2(GND1A) U10.8(GND1B)
GND_FLOAT: C91.2 C94.1 C95.2 C96.2 CN2.5 DL4.1(CATHODE) FB4.2 N41.1 U4.2(GND) U5.2(GND1A) U5.8(GND1B)
GND_POWER: U1.54(RESERVED_1) ; also on sheet 2 3 6 7
GND_SIGNAL: C84.2 C85.2 C86.2 C87.2 C88.2 C92.2 C93.2 C97.2 C98.2 C99.2 C100.2 C101.2 C102.2 C103.2 C105.2 C106.2 C110.2 C111.2 C112.2 C113.2 C114.2 C115.2 C116.2 C117.2 J17.4 J17.6 J17.8 J17.10 J17.12 J17.14 J17.16 J17.18 J17.20 J20.GND1 J20.GND2 J20.GND3 J20.GND4 J20.GND5 J20.GND6 J20.GND7 J20.GND8 J20.GND9 J20.GND10 J20.GND11 J20.GND12 J20.GND13 J20.GND14 J21.1 J22.3 J23.1 JP12.1 R76.1 R78.1 R79.1 R80.2 R187.2 S1.1 S1.2 SW1.3(B2) SW1.4(B1) U1.15(RESERVED_3) U1.102(ADC_VREFN) U1.155(RESERVED_2) U5.9(GND2B) U5.15(GND2A) U6.1(E0) U6.2(E1) U6.3(E2) U6.4(VSS) U6.7(nWC) U7.2(GND) U7.25(EPAD) U8.4(GND) U10.9(GND2B) U10.15(GND2A) U11.8(VSSA) U11.20(PB2/BOOT1) U11.23(VSS_1) U11.35(VSS_2) U11.44(BOOT0) U11.47(VSS_3) Y1.2(C2) Y1.4(C1) Y2.3(CASE) ; also on sheet 5 6 7
VBAT: J20.27 ; also on sheet 6 7
VCC_PSU: J20.1 J20.2 ; also on sheet 6
ATTACH: R201.1 U11.31(PA10)
GPIO00_0: J20.12 R89.1 ; also on sheet 5
GPIO00_1: J20.14 R95.1 ; also on sheet 5
GPIO00_2: J20.16 R91.1
GPIO00_3: J20.18 R92.1
GPIO00_4: J20.20 R93.1
GPIO00_5: J20.22 R109.1
GPIO00_6: J20.24 R112.1 R163.2
GPIO00_7: J20.26 R116.1 R161.2
GPIO01_0: J20.71 R120.1
GPIO01_1: J20.73 R123.1 R175.1
GPIO01_2: J20.75 R126.1 R174.1
GPIO01_3: J20.77 R129.1 R177.1
GPIO01_4: J20.79 R132.1 R176.1
GPIO01_5: J20.81 R135.1
GPIO01_6: J20.83 R137.1
GPIO01_7: J20.85 R139.1
GPIO02_0: J20.91 R94.2
GPIO02_1: J20.93 R101.2
GPIO02_2: J20.95 R102.2
GPIO02_3: J20.97 R104.2
GPIO02_4: J20.99 R106.2
GPIO02_5: J20.101 R110.2
GPIO02_6: J20.103 R113.2
GPIO02_7: J20.105 R117.2
GPIO03_0: J20.52 R121.2
GPIO03_1: J20.54 R124.2
GPIO03_2: J20.56 R127.2
GPIO03_3: J20.58 R130.2
GPIO03_4: J20.60 R133.2
GPIO03_5: J20.62 R136.2
GPIO03_6: J20.64 R138.2
GPIO03_7: J20.66 R140.2
GPIO04_0: J20.32 R90.1
GPIO04_1: J20.34 R96.1
GPIO04_2: J20.36 R98.1
GPIO04_3: J20.38 R99.1
GPIO04_4: J20.40 R107.1
GPIO04_5: J20.42 R100.1
GPIO04_6: J20.44 R114.1
GPIO04_7: J20.46 R118.1
GPIO05_0: J20.112 R122.1
GPIO05_1: J20.114 R125.1
GPIO05_2: J20.116 R128.1
GPIO05_3: J20.118 R131.1
GPIO05_4: J20.111 N39.1 R134.1
GPIO05_5: J20.113 R169.1 U1.128(GPIO05_5)
GPIO05_6: J20.115 R168.1 U1.127(GPIO05_6)
GPIO05_7: J20.117 R141.1
GPIO06_0: J20.11 U1.125(GPIO06_0)
GPIO06_1: J20.13 R97.2
GPIO06_2: J20.15 R103.2
GPIO06_3: J20.17 R105.2
GPIO06_4: J20.19 R108.2
GPIO06_5: J20.21 R111.2
GPIO06_6: J20.23 R115.2
GPIO06_7: J20.25 R119.2
GPIO07_0: J20.31 U1.117(GPIO07_0)
GPIO07_1: J20.33 U1.116(GPIO07_1)
GPIO07_2: J20.35 U1.115(GPIO07_2)
GPIO07_3: J20.37 U1.114(GPIO07_3)
GPIO07_4: J20.39 U1.113(GPIO07_4)
GPIO07_5: J20.41 U1.112(GPIO07_5)
GPIO07_6: J20.43 U1.111(GPIO07_6)
GPIO07_7: J20.45 R142.2
GPIO08_0: J20.51 R143.2 U1.109(GPIO08_0)
GPIO08_0_L: DL9.1(CATHODE) R143.1 R182.1
GPIO08_1: J20.53 R144.2 R148.1
GPIO08_1_L: DL10.1(CATHODE) R144.1 R184.1
GPIO08_2: J20.55 R145.2 U1.107(GPIO08_2)
GPIO08_2_L: DL11.1(CATHODE) R145.1 R185.1
GPIO08_3: J20.57 R146.2 U1.106(GPIO08_3)
GPIO08_3_L: DL12.1(CATHODE) R146.1 R186.1
GPIO08_4: J20.59 R147.1
GPIO08_5: J20.61 R149.1
GPIO09_0: J20.72 U1.82(GPIO09_0)
GPIO09_1: J20.74 U1.81(GPIO09_1)
GPIO09_2: J20.76 U1.80(GPIO09_2)
GPIO09_3: J20.78 N40.1 R153.1
GPIO09_4: J20.80 U1.78(GPIO09_4)
GPIO09_5: J20.82 U1.77(GPIO09_5)
GPIO09_6: J20.84 R154.1
GPIO09_7: J20.86 R155.1
GPIO10_0: J20.92 U1.71(GPIO10_0)
GPIO10_1: J20.94 U1.70(GPIO10_1)
GPIO10_2: J20.96 U1.69(GPIO10_2)
GPIO10_3: J20.98 U1.68(GPIO10_3)
GPIO10_4: J20.100 U1.67(GPIO10_4)
GPIO10_5: J20.102 R150.2
GPIO10_6: J20.104 R151.2
GPIO10_7: J20.106 R152.2
J_TCK: J17.9 R80.1 R200.2 U1.21(JTAG_TCK)
J_TDI: J17.5 R199.2 U1.19(JTAG_TDI)
J_TDO: J17.13 R71.2 R201.2 U1.22(JTAG_TDO)
J_TMS: J17.7 R202.2 U1.20(JTAG_TMS)
J_TRSTN: J17.3 R70.2 R197.2 U1.18(JTAG_TRSTN)
MRESET_JTAG: J17.15 R88.2 R198.2
RESET_J-LINK: C110.1 J22.10 J23.2 N51.1 U11.7(NRST)
RESETN: C84.1 C86.1 J20.65 R64.2 R88.1 R183.2 S1.3 S1.4 U1.74(RESETN)
SPI0_MISO: R181.1 U1.10(SPI0_MISO)
SPI0_MOSI: R77.2 U8.5(SI)
SPI0_SCLK: R81.2 U8.6(SCK)
SPI0_SSn: R178.2 U1.8(SPI0_SSn) U8.1(~{CS})
TAMPER_A: J20.120 U1.97(RTC_TAMPA)
TAMPER_B: J20.119 U1.96(RTC_TAMPB)
TCKS: J22.4 N54.1 U11.37(PA14)
TDIS: J22.8 N52.1 U11.38(PA15)
TDOS: J22.6 N53.1 U11.39(PB3/JTDO)
TMSS: J22.2 N55.1 U11.34(PA13)
TRSTS: J22.9 N56.1 U11.40(PB4/JNTRST)
USART0_RXD: R165.1 TP35.1 U1.6(USART0_RXD)
USART0_TXD: R167.1 TP36.1 U1.7(USART0_TXD)
USB+: R164.1 U7.3(D+)
USB+_J-LINK: R196.1 R204.2 U11.33(PA12)
USB-: R162.2 U7.4(D-)
USB-_J-LINK: R195.2 U11.32(PA11)
USB_F+: R160.1 U5.7(UD+)
USB_F+_J-link: R194.1 U10.7(UD+)
USB_F-: R157.2 U5.6(UD-)
USB_F-_J-link: R193.2 U10.6(UD-)
USB_VBUS: C91.1 C96.1 FB3.2 R156.1 U4.5(VBUS) U5.1(VBUS1)
USB_VBUS_J: C104.1 C109.1 FB5.2 R192.1 U9.5(VBUS) U10.1(VBUS1)
N19706874: C85.1 R65.2 U1.103(ADC_VREFP)
N19707029: U1.100(OSC32_OUT) Y2.2
N19707034: U1.101(OSC32_IN) Y2.1
N19707192: C88.1 U1.26(MCLK_OUT) Y1.3
N19707198: C87.1 U1.25(MCLK_IN) Y1.1
N19709602: R66.2 SW1.2(A2) U1.17(BOOT1)
N19709611: R67.2 SW1.1(A1) U1.16(BOOT0)
N19716531: R77.1 U1.11(SPI0_MOSI)
N19716578: R81.1 U1.9(SPI0_SCLK)
N19769586: R157.1 U4.3(I/O2#3)
N19769588: R160.2 U4.1(I/O1#1)
N19770000: DL4.2(ANODE) R156.2
N19770552: R166.2 U7.9(RSTN)
N19770635: C102.1 U7.16(NC/DCD_ECI/VPP)
N19771050: C94.2 U5.3(VDD1) U5.4(PDEN) U5.5(SPU)
N19771538: C95.1 CN2.1 FB3.1 N44.1
N19773533: CN2.3 N42.1 U4.6(I/O1#6)
N19773542: CN2.2 N43.1 U4.4(I/O2#4)
N19774770: R162.1 U5.11(DD-)
N19774775: R164.2 U5.10(DD+)
N19775879: R169.2 U7.10(CTS_ECI)
N19775880: R167.2 U7.12(RXD_ECI)
N19775881: R165.2 U7.13(TXD_ECI)
N19775882: R168.2 U7.11(RTS_ECI)
N19775998: R177.2 U7.18(CTS_SCI)
N19776000: R175.2 U7.20(RXD_SCI)
N19776002: R174.2 U7.21(TXD_SCI)
N19776004: R176.2 U7.19(RTS_SCI)
N19819722: R89.2 U1.5(GPIO00_0)
N19819725: R95.2 U1.3(GPIO00_1)
N19819728: R91.2 U1.2(GPIO00)
N19819731: R92.2 U1.1(GPIO00_3)
N19819855: R93.2 U1.176(GPIO00_4)
N19819857: R109.2 U1.174(GPIO00_5)
N19819873: R112.2 U1.173(GPIO00_6)
N19819875: R116.2 U1.172(GPIO00_7)
N19820071: R120.2 U1.171(GPIO01_0)
N19820073: R123.2 U1.170(GPIO01_1)
N19820089: R126.2 U1.169(GPIO01_2)
N19820091: R129.2 U1.168(GPIO01_3)
N19820113: R132.2 U1.167(GPIO01_4)
N19820119: R135.2 U1.166(GPIO01_5)
N19820135: R137.2 U1.165(GPIO01_6)
N19820137: R139.2 U1.164(GPIO01_7)
N19820455: R90.2 U1.143(GPIO04_0)
N19820457: R96.2 U1.142(GPIO04_1)
N19820473: R98.2 U1.141(GPIO04_2)
N19820475: R99.2 U1.140(GPIO04_3)
N19820497: R107.2 U1.139(GPIO04_4)
N19820503: R100.2 U1.138(GPIO04_5)
N19820519: R114.2 U1.137(GPIO04_6)
N19820521: R118.2 U1.136(GPIO04_7)
N19820543: R122.2 U1.134(GPIO05_0)
N19820545: R125.2 U1.133(GPIO05_1)
N19820551: R128.2 U1.132(GPIO05_2)
N19820553: R131.2 U1.131(GPIO05_3)
N19820971: R94.1 U1.163(GPIO02_0)
N19820973: R101.1 U1.162(GPIO02_1)
N19820989: R102.1 U1.161(GPIO02_2)
N19820991: R104.1 U1.160(GPIO02_3)
N19821013: R106.1 U1.159(GPIO02_4)
N19821019: R110.1 U1.158(GPIO02_5)
N19821035: R113.1 U1.157(GPIO02_6)
N19821037: R117.1 U1.156(GPIO02_7)
N19821059: R121.1 U1.151(GPIO03_0)
N19821061: R124.1 U1.150(GPIO03_1)
N19821067: R127.1 U1.149(GPIO03_2)
N19821069: R130.1 U1.148(GPIO03_3)
N19935675: CN2.SH1 CN2.SH2 FB4.1
N19990698: R134.2 U1.129(GPIO05_4)
N21452929: CN3.SH1 CN3.SH2 FB6.1
N21452947: C107.2 U10.3(VDD1) U10.4(PDEN) U10.5(SPU)
N21453074: R193.1 U9.3(I/O2#3)
N21453076: R194.2 U9.1(I/O1#1)
N21453152: DL13.2(ANODE) R192.2
N21453255: C108.1 CN3.1 FB5.1 N48.1
N21453259: CN3.3 N46.1 U9.6(I/O1#6)
N21453265: CN3.2 N47.1 U9.4(I/O2#4)
N21453369: R195.1 U10.11(DD-)
N21453371: R196.2 U10.10(DD+)
N21457609: DL9.2(ANODE) R188.2
N21457643: DL10.2(ANODE) R189.2
N21457648: DL11.2(ANODE) R190.2
N21457669: DL12.2(ANODE) R191.2
N21460077: R197.1 U11.10(PA0-WKUP)
N21460138: R198.1 U11.11(PA1)
N21461364: R199.1 U11.12(PA2)
N21461379: R200.1 U11.15(PA5)
N21461440: R202.1 U11.17(PA7)
N21461789: C111.1 R205.2 U11.5(OSCIN/PD0) Y3.1
N21461841: C112.1 R205.1 U11.6(OSCOUT/PD1) Y3.2
N21462973: R204.1 U11.30(PA9)
N21463857: J21.2 U11.41(PB5)
N21466458: DL14.2(ANODE) R203.1
N21466767: DL14.1(CATHODE) U11.29(PA8)
N21469872: J17.2 R69.2
N21469876: J17.11 R76.2
N21469934: J17.17 R79.2
N21469953: J17.19 R78.2 TP13.1
N21479522: R147.2 U1.105(GPIO08_4)
N21479525: R149.2 U1.104(GPIO08_5)
N21490371: R158.1 R161.1 U6.6(SCL)
N21490383: R159.1 R163.1 U6.5(SDA)
N21491474: R180.2 R183.1 U8.7(~{RESET})
N21491476: R179.2 R187.1 U8.3(~{WP})
N21491488: R181.2 U8.2(SO)
N21496243: R152.1 U1.64(GPIO10_7)
N21497359: R133.1 U1.147(GPIO03_4)
N21497362: R136.1 U1.146(GPIO03_5)
N21497365: R138.1 U1.145(GPIO03_6)
N21497368: R140.1 U1.144(GPIO03_7)
N21513611: J22.1 JP11.1
N21693220: R153.2 U1.79(GPIO09_3)
N21695278: R141.2 U1.126(GPIO05_7)
N21695523: R103.1 U1.123(GPIO06_2)
N21695550: R105.1 U1.122(GPIO06_3)
N21695643: R119.1 U1.118(GPIO06_7)
N21695644: R115.1 U1.119(GPIO06_6)
N21695645: R111.1 U1.120(GPIO06_5)
N21695646: R108.1 U1.121(GPIO06_4)
N21695767: R142.1 U1.110(GPIO07_7)
N21695796: R97.1 U1.124(GPIO06_1)
N21750507: R172.2 U7.24(GPIO0_SCI/DCD_SCI)
N21750517: R173.2 U7.23(GPIO1_SCI/DTR_SCI)
N21750590: R170.2 U7.15(GPIO0_ECI/DTR_ECI)
N21750593: R171.2 U7.14(GPIO1_ECI/DSR_ECI)
N21845623: R155.2 U1.75(GPIO09_7)
N21845645: R151.1 U1.65(GPIO10_6)
N21845681: R154.2 U1.76(GPIO09_6)
N21845754: R148.2 U1.108(GPIO08_1)
N21845869: R150.1 U1.66(GPIO10_5)
N21899173: DL6.1(CATHODE) R170.1
N21899174: DL5.1(CATHODE) R172.1
N21899175: DL8.1(CATHODE) R173.1
N21899176: DL7.1(CATHODE) R171.1
N21907733: J20.28 TP15.1
N21907984: J20.87 TP28.1
N21907986: J20.88 TP27.1
N21908006: J20.63 TP22.1
N21908090: J20.30 TP14.1
N21908092: J20.29 TP17.1
N21908106: J20.48 TP18.1
N21908108: J20.47 TP19.1
N21908122: J20.50 TP20.1
N21908124: J20.49 TP21.1
N21908138: J20.68 TP23.1
N21908140: J20.67 TP24.1
N21908154: J20.70 TP25.1
N21908156: J20.69 TP26.1
N21908170: J20.90 TP29.1
N21908172: J20.89 TP30.1
N21908186: J20.108 TP31.1
N21908188: J20.107 TP32.1
N21908202: J20.110 TP33.1
N21908204: J20.109 TP34.1
N22037790: J22.5 JP12.2

Not connected (* = marked no-connect by the designer): CN2 4*; CN3 4*; U7 1(SUSPENDN/RI_SCI)* 17(SUSPENDN/RI_ECI)* 22(GPIO2_SCI/DSR_SCI)*; U11 2(PC13-TAMPER-RTC)* 3(PC14-OSC32_IN)* 4(PC15-OSC32_OUT)* 13(PA3)* 14(PA4)* 16(PA6)* 18(PB0)* 19(PB1)* 21(PB10)* 22(PB11)* 25(PB12)* 26(PB13)* 27(PB14)* 28(PB15)* 42(PB6)* 43(PB7)* 45(PB8)* 46(PB9)*

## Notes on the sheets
sheet 8
- RESET
- BOOT
- 1
- 0
- BOOT0
- BOOT1
- COMET reset, clock, JTAG, BOOT modes, ADC reference
- JTAG
- 47K for J-link OB
- !! CAUTION!!
  JTAG connector
  to be mounted
  on bottom side
- Place R100 & R104 near U1
- + Hatched area
- Optional internall pull-up
  on SPI0_SS of 40k
- JTAG
  CONNECTOR
- COMET SPI0, UART0, Tamper dect.
- JTAG & ETM connectors
sheet 9
- Optional resistors to eventually damp
  the FSMC  lines
- MCO1
- COMET GPIOs
- MCO2
- R153 to be placed near COMET
sheet 10
- GPIO Assigned
  on main board
- GPIO Assigned
  on main board
- RELAY_A
- RELAY_B
- I2C0_SCL
- I2C0_SDA
- METR_CMD1
- METR_CMD2
- USART1_TXD
- USART1_RXD
- METR_LED0
- USART1_RTS
- METR_LED1
- USART1_CTS
- METR_ZCOUT
- USART0_RTS
- USART0_CTS
- RECEPTACLE 120 Pins CONNECTOR
sheet 11
- UARTs
- I2C0_SCL
- I2C0_SDA
- USART0
- USART1
- 512kbit METROLOGY EEPROM
  I2C0
- Tx
- Rx
- Tx
- Rx
- USART0_CTS
- USART0_RTS
- USART1_RXD
- USART1_TXD
- USART1_CTS
- USART1_RTS
- Insulated UART0 & UART1 over USB bridge
  GPIO01_[1..4] & GPIO05_[5,6]
- 4.7uF
- Place R220 near U8
- G8.0
- G8.1
- G8.2
- G8.3
- 16Mbit BOOT FLASH
  SPI0
- LED GPIO[08_0..08_3]
sheet 12
- J-LINK OB
- J-Link Technology
                          www.segger.com
- Open to enable J-Link OB
- Cut pin 7 on
  the connector
- Force J-link Reset
- JTAG on board programming connector
